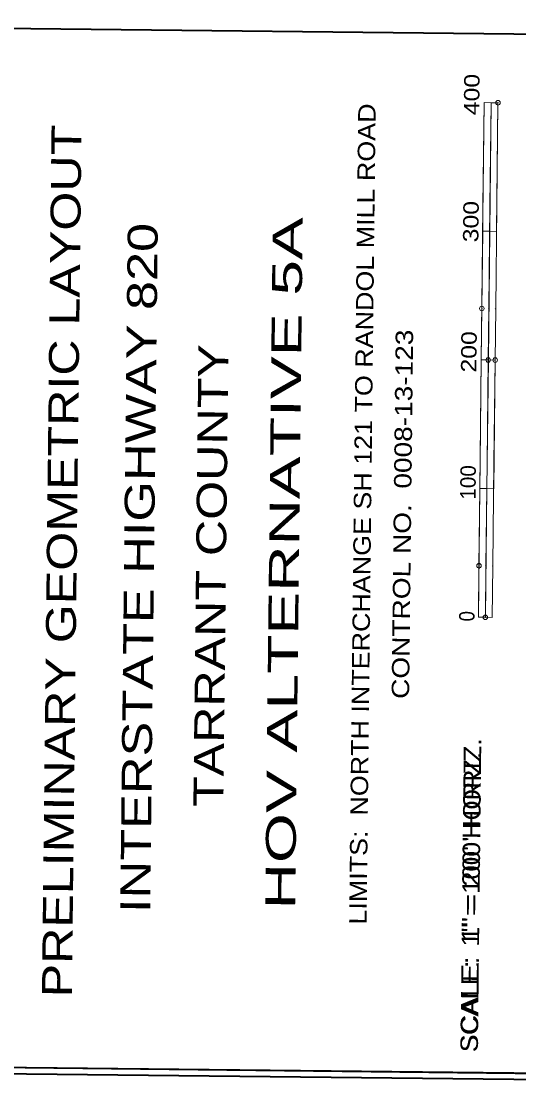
# Model space of a CAD drawing. Extents: x 2356576 to 2377878, y 6966390 to 6990634.
# Drawn here: x 2366242 to 2366630, y 6968641 to 6969467 of the extents above; entities that cross this region are included whole.
import ezdxf

# ---------------------------------------------------------------- set-up
doc = ezdxf.new("R2010")
doc.units = 0
doc.header["$LTSCALE"] = 7.1
doc.header["$PDMODE"] = 32
doc.header["$PDSIZE"] = 3.55
doc.layers.add('19', color=7, linetype='Continuous', lineweight=13)
doc.layers.add('8', color=7, linetype='Continuous', lineweight=13)

msp = doc.modelspace()

# ---------------------------------------------------------------- linework, layer by layer
at = {"layer": '19', "lineweight": 35}
for p, q in [((2366931.855, 6969453.45), (2366226.339, 6969461.286)), ((2366217.375, 6968654.072), (2366922.891, 6968646.236))]:
    msp.add_line(p, q, dxfattribs=at)
at = {"layer": '19'}
for p, q in [((2366598.134, 6969003.772), (2366600.354, 6969203.761)), ((2366599.466, 6969123.765), (2366600.354, 6969203.761)), ((2366605.748, 6969203.701), (2366600.354, 6969203.761)), ((2366605.747, 6969203.701), (2366600.354, 6969203.761)), ((2366605.745, 6969203.42), (2366606.029, 6969203.698)), ((2366605.746, 6969203.514), (2366605.935, 6969203.699)), ((2366611.14, 6969203.641), (2366605.747, 6969203.701)), ((2366605.747, 6969203.608), (2366605.841, 6969203.7)), ((2366605.829, 6969203.7), (2366605.748, 6969203.783)), ((2366605.924, 6969203.699), (2366605.749, 6969203.877)), ((2366611.142, 6969203.641), (2366610.253, 6969123.645)), ((2366611.138, 6969203.333), (2366610.834, 6969203.645)), ((2366610.888, 6969203.644), (2366611.143, 6969203.893)), ((2366611.139, 6969203.428), (2366610.928, 6969203.643)), ((2366610.982, 6969203.643), (2366611.142, 6969203.799)), ((2366611.14, 6969203.522), (2366611.022, 6969203.642)), ((2366611.141, 6969203.616), (2366611.116, 6969203.642)), ((2366598.578, 6969043.77), (2366599.466, 6969123.765)), ((2366599.466, 6969123.721), (2366599.51, 6969123.765)), ((2366604.859, 6969123.705), (2366603.971, 6969043.71)), ((2366609.364, 6969043.65), (2366610.253, 6969123.645)), ((2366599.244, 6969103.766), (2366610.031, 6969103.646)), ((2366598.134, 6969003.772), (2366598.578, 6969043.77)), ((2366598.668, 6969043.769), (2366598.579, 6969043.86)), ((2366598.762, 6969043.768), (2366598.58, 6969043.954)), ((2366603.527, 6969003.712), (2366603.971, 6969043.71)), ((2366603.757, 6969043.712), (2366603.974, 6969043.924)), ((2366603.851, 6969043.711), (2366603.972, 6969043.829)), ((2366603.946, 6969043.71), (2366603.971, 6969043.735)), ((2366603.97, 6969043.634), (2366604.046, 6969043.709)), ((2366603.97, 6969043.54), (2366604.14, 6969043.708)), ((2366609.361, 6969043.31), (2366609.025, 6969043.654)), ((2366609.362, 6969043.405), (2366609.12, 6969043.653)), ((2366603.527, 6969003.712), (2366598.134, 6969003.772)), ((2366603.609, 6969003.711), (2366603.528, 6969003.794)), ((2366603.704, 6969003.71), (2366603.529, 6969003.888)), ((2366608.668, 6969003.655), (2366608.923, 6969003.904)), ((2366608.762, 6969003.654), (2366608.922, 6969003.81))]:
    msp.add_line(p, q, dxfattribs=at)
at = {"layer": '19', "lineweight": 40}
msp.add_lwpolyline([(2363758.773, 6990629.355), (2367158.576, 6990592.767), (2366922.891, 6968646.236), (2363523.088, 6968682.826)], close=True, dxfattribs=at)
at = {"layer": '19'}
for points in [[(2366604.753, 6969103.725), (2366605.863, 6969203.7), (2366611.142, 6969203.641), (2366610.031, 6969103.666)], [(2366598.134, 6969003.772), (2366599.244, 6969103.786), (2366604.753, 6969103.725), (2366603.642, 6969003.71)]]:
    msp.add_lwpolyline(points, close=True, dxfattribs=at)
for points in [[(2366604.859, 6969123.705), (2366605.748, 6969203.701), (2366611.142, 6969203.641)], [(2366609.364, 6969043.65), (2366608.92, 6969003.652), (2366603.527, 6969003.712)]]:
    msp.add_lwpolyline(points, dxfattribs=at)
for p in [(2366605.747, 6969203.701), (2366611.142, 6969203.641), (2366598.578, 6969043.77), (2366603.527, 6969003.712)]:
    msp.add_point(p, dxfattribs=at)
at = {"layer": '8', "lineweight": 35}
for p, q in [((2366931.855, 6969453.45), (2366226.339, 6969461.286)), ((2366217.375, 6968654.072), (2366922.891, 6968646.236))]:
    msp.add_line(p, q, dxfattribs=at)
at = {"layer": '8'}
for p, q in [((2366600.354, 6969203.761), (2366602.574, 6969403.75)), ((2366601.686, 6969323.754), (2366602.574, 6969403.75)), ((2366607.968, 6969403.69), (2366602.574, 6969403.75)), ((2366607.965, 6969403.409), (2366608.249, 6969403.687)), ((2366607.966, 6969403.503), (2366608.155, 6969403.688)), ((2366607.967, 6969403.597), (2366608.061, 6969403.689)), ((2366613.362, 6969403.63), (2366612.473, 6969323.634)), ((2366613.358, 6969403.322), (2366613.054, 6969403.634)), ((2366613.359, 6969403.417), (2366613.148, 6969403.632)), ((2366613.36, 6969403.511), (2366613.242, 6969403.631)), ((2366613.361, 6969403.605), (2366613.336, 6969403.631)), ((2366600.798, 6969243.759), (2366601.686, 6969323.754)), ((2366601.686, 6969323.71), (2366601.73, 6969323.754)), ((2366607.079, 6969323.694), (2366606.191, 6969243.699)), ((2366611.584, 6969243.639), (2366612.473, 6969323.634)), ((2366601.464, 6969303.755), (2366612.251, 6969303.635)), ((2366600.354, 6969203.761), (2366600.798, 6969243.759)), ((2366600.888, 6969243.758), (2366600.799, 6969243.849)), ((2366600.982, 6969243.757), (2366600.8, 6969243.943)), ((2366605.747, 6969203.701), (2366606.191, 6969243.699)), ((2366605.977, 6969243.701), (2366606.194, 6969243.913)), ((2366606.071, 6969243.7), (2366606.192, 6969243.818)), ((2366606.166, 6969243.699), (2366606.191, 6969243.724)), ((2366606.19, 6969243.623), (2366606.266, 6969243.698)), ((2366606.19, 6969243.529), (2366606.36, 6969243.697)), ((2366611.581, 6969243.299), (2366611.245, 6969243.643)), ((2366611.582, 6969243.394), (2366611.34, 6969243.642)), ((2366598.134, 6969003.772), (2366600.354, 6969203.761)), ((2366599.466, 6969123.765), (2366600.354, 6969203.761)), ((2366605.748, 6969203.701), (2366600.354, 6969203.761)), ((2366605.747, 6969203.701), (2366600.354, 6969203.761)), ((2366605.745, 6969203.42), (2366606.029, 6969203.698)), ((2366605.746, 6969203.514), (2366605.935, 6969203.699)), ((2366605.747, 6969203.608), (2366605.841, 6969203.7)), ((2366605.829, 6969203.7), (2366605.748, 6969203.783)), ((2366605.924, 6969203.699), (2366605.749, 6969203.877)), ((2366611.142, 6969203.641), (2366610.253, 6969123.645)), ((2366611.138, 6969203.333), (2366610.834, 6969203.645)), ((2366610.888, 6969203.644), (2366611.143, 6969203.893)), ((2366611.139, 6969203.428), (2366610.928, 6969203.643)), ((2366610.982, 6969203.643), (2366611.142, 6969203.799)), ((2366611.14, 6969203.522), (2366611.022, 6969203.642)), ((2366611.141, 6969203.616), (2366611.116, 6969203.642)), ((2366598.578, 6969043.77), (2366599.466, 6969123.765)), ((2366599.466, 6969123.721), (2366599.51, 6969123.765)), ((2366604.859, 6969123.705), (2366603.971, 6969043.71)), ((2366609.364, 6969043.65), (2366610.253, 6969123.645)), ((2366599.244, 6969103.766), (2366610.031, 6969103.646)), ((2366598.134, 6969003.772), (2366598.578, 6969043.77)), ((2366598.668, 6969043.769), (2366598.579, 6969043.86)), ((2366598.762, 6969043.768), (2366598.58, 6969043.954)), ((2366603.527, 6969003.712), (2366603.971, 6969043.71)), ((2366603.757, 6969043.712), (2366603.974, 6969043.924)), ((2366603.851, 6969043.711), (2366603.972, 6969043.829)), ((2366603.946, 6969043.71), (2366603.971, 6969043.735)), ((2366603.97, 6969043.634), (2366604.046, 6969043.709)), ((2366603.97, 6969043.54), (2366604.14, 6969043.708)), ((2366609.361, 6969043.31), (2366609.025, 6969043.654)), ((2366609.362, 6969043.405), (2366609.12, 6969043.653)), ((2366603.527, 6969003.712), (2366598.134, 6969003.772)), ((2366603.609, 6969003.711), (2366603.528, 6969003.794)), ((2366603.704, 6969003.71), (2366603.529, 6969003.888)), ((2366608.668, 6969003.655), (2366608.923, 6969003.904)), ((2366608.762, 6969003.654), (2366608.922, 6969003.81))]:
    msp.add_line(p, q, dxfattribs=at)
at = {"layer": '8', "lineweight": 40}
for points in [[(2363753.827, 6990634.409), (2367163.63, 6990597.713), (2366927.837, 6968641.182), (2363518.034, 6968677.88)], [(2363758.773, 6990629.355), (2367158.576, 6990592.767), (2366922.891, 6968646.236), (2363523.088, 6968682.826)]]:
    msp.add_lwpolyline(points, close=True, dxfattribs=at)
at = {"layer": '8'}
for points in [[(2366606.973, 6969303.714), (2366608.083, 6969403.689), (2366613.362, 6969403.63), (2366612.251, 6969303.655)], [(2366600.354, 6969203.761), (2366601.464, 6969303.775), (2366606.973, 6969303.714), (2366605.862, 6969203.699)], [(2366604.753, 6969103.725), (2366605.863, 6969203.7), (2366611.142, 6969203.641), (2366610.031, 6969103.666)], [(2366598.134, 6969003.772), (2366599.244, 6969103.786), (2366604.753, 6969103.725), (2366603.642, 6969003.71)]]:
    msp.add_lwpolyline(points, close=True, dxfattribs=at)
for points in [[(2366607.079, 6969323.694), (2366607.968, 6969403.69), (2366613.362, 6969403.63)], [(2366611.584, 6969243.639), (2366611.14, 6969203.641), (2366605.747, 6969203.701)], [(2366604.859, 6969123.705), (2366605.748, 6969203.701), (2366611.142, 6969203.641)], [(2366609.364, 6969043.65), (2366608.92, 6969003.652), (2366603.527, 6969003.712)]]:
    msp.add_lwpolyline(points, dxfattribs=at)
for p in [(2366613.362, 6969403.63), (2366600.798, 6969243.759), (2366605.747, 6969203.701), (2366611.142, 6969203.641), (2366598.578, 6969043.77), (2366603.527, 6969003.712)]:
    msp.add_point(p, dxfattribs=at)

# ---------------------------------------------------------------- texts
at = {"layer": '19'}
for s, height, width, p in [('LIMITS:  NORTH INTERCHANGE SH 121 TO RANDOL MILL ROAD', 13.58, 1.15, (2366511.131, 6968764.848)), ('PRELIMINARY GEOMETRIC LAYOUT', 23.33, 1.25, (2366281.849, 6968708.22)), (' HOV ALTERNATIVE 5A', 23.33, 1.6, (2366455.363, 6968762.672)), ('INTERSTATE HIGHWAY 820', 23.33, 1.3, (2366342.763, 6968773.78)), ('CONTROL NO.  0008-13-123', 13.58, 1.2, (2366544.185, 6968940.228)), ('200', 12, 1.2, (2366596.522, 6969193.885)), ('TARRANT COUNTY', 23.33, 1.25, (2366399.671, 6968856.176)), ('0', 12, 0.9, (2366595.056, 6969000.469)), ('SCALE:  1" = 100\' HORIZ.', 13.58, 1.1, (2366597.695, 6968665.624))]:
    msp.add_text(s, height=height, rotation=89.364, dxfattribs=dict(at, width=width)).set_placement(p)
msp.add_text('100', height=12, rotation=89.364, dxfattribs=at).set_placement((2366595.876, 6969095.121))
at = {"layer": '8'}
for s, height, width, p in [('400', 12, 1.2, (2366598.742, 6969393.874)), ('LIMITS:  NORTH INTERCHANGE SH 121 TO RANDOL MILL ROAD', 13.58, 1.15, (2366511.131, 6968764.848)), ('PRELIMINARY GEOMETRIC LAYOUT', 23.33, 1.25, (2366281.849, 6968708.22)), ('300', 12, 1.2, (2366598.096, 6969295.11)), (' HOV ALTERNATIVE 5A', 23.33, 1.6, (2366455.363, 6968762.672)), ('INTERSTATE HIGHWAY 820', 23.33, 1.3, (2366342.763, 6968773.78)), ('CONTROL NO.  0008-13-123', 13.58, 1.2, (2366544.185, 6968940.228)), ('200', 12, 1.2, (2366596.522, 6969193.885)), ('TARRANT COUNTY', 23.33, 1.25, (2366399.671, 6968856.176)), ('0', 12, 0.9, (2366595.056, 6969000.469)), ('SCALE:  1" = 200\' HORIZ.', 13.58, 1.15, (2366597.695, 6968665.624))]:
    msp.add_text(s, height=height, rotation=89.364, dxfattribs=dict(at, width=width)).set_placement(p)
msp.add_text('100', height=12, rotation=89.364, dxfattribs=at).set_placement((2366595.876, 6969095.121))

doc.saveas('drawing.dxf')
